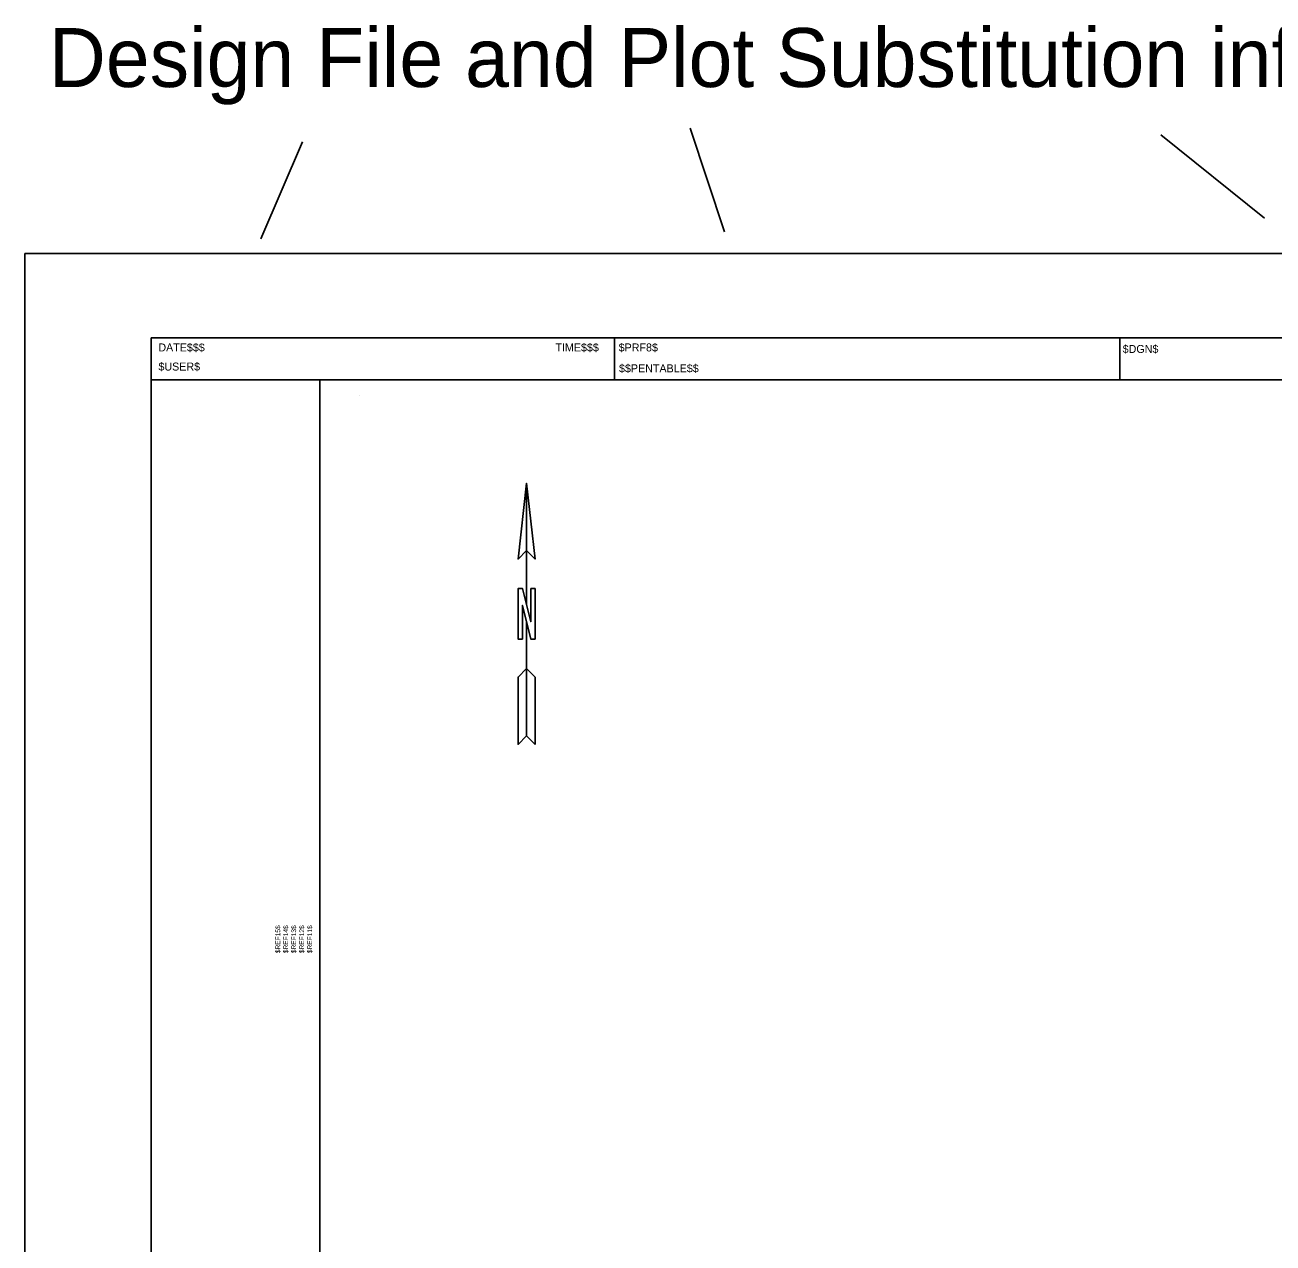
# Model space of a CAD drawing. Extents: x 2157704 to 2158404, y 1040586 to 1041166.
# Drawn here: x 2157704 to 2158000.4, y 1040877.1 to 1041166.5 of the extents above; entities that cross this region are included whole.
import ezdxf

# ---------------------------------------------------------------- set-up
doc = ezdxf.new("R2010")
doc.units = 0
for name, color, linetype in [('SHT_B_Minor-Offset-Tic-Line', 7, 'Continuous'), ('SHT_B_Minor-Station-Tic-Line', 7, 'Continuous'), ('SHT_B_North-Arrow', 7, 'Continuous'), ('UTLE_E_UG-Wat-Line-30-Qual-B-50', 7, 'Continuous'), ('UTLE_E_UG-Wat-Line-30-Qual-C-50', 7, 'Continuous')]:
    doc.layers.add(name, color=color, linetype=linetype)

msp = doc.modelspace()

# ---------------------------------------------------------------- linework, layer by layer
at = {"layer": 'SHT_B_Minor-Offset-Tic-Line'}
for points in [[(2157823.12, 1041041.59), (2157825.12, 1041039.59), (2157823.12, 1041057.59), (2157821.12, 1041039.59)], [(2157824.12, 1041032.59), (2157825.12, 1041032.59), (2157825.12, 1041020.59), (2157824.12, 1041020.59), (2157822.12, 1041028.59), (2157822.12, 1041020.59), (2157821.12, 1041020.59), (2157821.12, 1041032.59), (2157822.16, 1041032.59), (2157824.12, 1041024.71)], [(2157825.12, 1040995.57), (2157825.12, 1041011.57), (2157823.12, 1041013.57), (2157821.12, 1041011.57), (2157821.12, 1040995.57), (2157823.12, 1040997.57)]]:
    msp.add_lwpolyline(points, close=True, dxfattribs=at)
for points in [[(2157823.12, 1041028.71), (2157823.12, 1041057.59)], [(2157823.12, 1040997.57), (2157823.12, 1041024.59)]]:
    msp.add_lwpolyline(points, dxfattribs=at)
at = {"layer": 'SHT_B_North-Arrow'}
for p, q in [((2157861.93, 1041141.97), (2157870.15, 1041117.31)), ((2157973.71, 1041140.33), (2157998.35, 1041120.59)), ((2157769.87, 1041138.69), (2157760.01, 1041115.67)), ((2157843.99, 1041082.15), (2157843.99, 1041092.15)), ((2157963.99, 1041082.15), (2157963.99, 1041092.15)), ((2158393.99, 1041082.15), (2157733.99, 1041082.15)), ((2157773.99, 1041082.15), (2157773.99, 1040672.15)), ((2157783.99, 1041082.15), (2157783.99, 1041082.15)), ((2157783.99, 1041082.15), (2157783.99, 1041082.15)), ((2157783.48, 1041078.35), (2157783.48, 1041078.35))]:
    msp.add_line(p, q, dxfattribs=at)
at = {"layer": 'UTLE_E_UG-Wat-Line-30-Qual-B-50'}
msp.add_lwpolyline([(2157733.99, 1041092.15), (2158393.99, 1041092.15), (2158393.99, 1040672.15), (2157733.99, 1040672.15)], close=True, dxfattribs=at)
at = {"layer": 'UTLE_E_UG-Wat-Line-30-Qual-C-50'}
msp.add_lwpolyline([(2157703.99, 1041112.15), (2158403.99, 1041112.15), (2158403.99, 1040652.15), (2157703.99, 1040652.15)], close=True, dxfattribs=at)

# ---------------------------------------------------------------- texts
at = {"layer": 'SHT_B_Minor-Station-Tic-Line'}
for s, height, rotation, p in [('DATE$$$', 1.9, 0, (2157735.67, 1041088.91)), ('TIME$$$', 1.9, 0, (2157829.97, 1041088.91)), ('$PRF8$', 1.9, 0, (2157844.99, 1041088.91)), ('$DGN$', 1.9, 0, (2157964.69, 1041088.55)), ('$USER$', 1.9, 0, (2157735.69, 1041084.37)), ('$$PENTABLE$$', 1.9001, 0, (2157845.07, 1041083.95)), ('$REF15$', 1.134, 90.0013, (2157764.61, 1040945.97)), ('$REF14$', 1.134, 90.0013, (2157766.49, 1040945.97)), ('$REF13$', 1.134, 90.0013, (2157768.39, 1040945.97)), ('$REF12$', 1.134, 90.0013, (2157770.29, 1040945.97)), ('$REF11$', 1.134, 90.0013, (2157772.19, 1040945.97))]:
    msp.add_text(s, height=height, rotation=rotation, dxfattribs=at).set_placement(p)
at = {"layer": 'SHT_B_North-Arrow'}
msp.add_text('Design File and Plot Substitution information', height=14, rotation=0, dxfattribs=at).set_placement((2157709.67, 1041151.73))

doc.saveas('drawing.dxf')
